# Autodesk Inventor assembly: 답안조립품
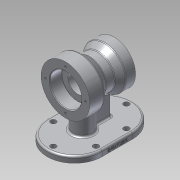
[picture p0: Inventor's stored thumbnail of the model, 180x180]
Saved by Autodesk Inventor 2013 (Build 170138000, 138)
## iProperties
Created: 2020-01
Part Number: 답안조립품
Document SubType Name: Assembly
Designer: Administrator
Author: Administrator
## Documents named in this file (2)
- C:\Users\Administrator\Desktop\700104V1022\답안조립품.iam
- C:\Users\Administrator\Desktop\700104V1022\본체.ipt
